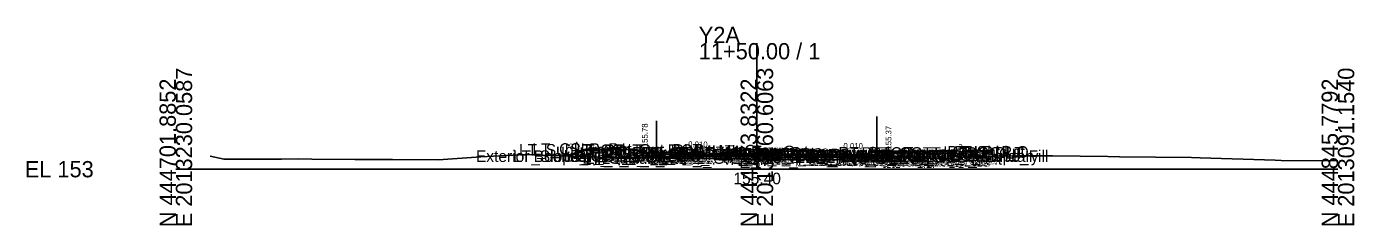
# Model space of a CAD drawing. Extents: x -26 to 203, y -10 to 5517.
# Drawn here: x -25.7 to 202.8, y 2990.3 to 3024.6 of the extents above; entities that cross this region are included whole.
import ezdxf

# ---------------------------------------------------------------- set-up
doc = ezdxf.new("R2010")
doc.units = 0
for name, color, linetype in [('Default', 7, 'Continuous'), ('Exist Cross Section Cell', 7, 'Continuous'), ('Exist XS Center Line Elevation Label', 7, 'Continuous'), ('Exist XS Ground Line', 7, 'Continuous'), ('Prop CMT Conc Surface', 7, 'Continuous'), ('Prop CMT Concrete Structures', 7, 'Continuous'), ('Prop CMT Pvmt Course 1', 7, 'Continuous'), ('Prop CMT Pvmt Course 1 CG', 7, 'Continuous'), ('Prop CMT Pvmt Course 2', 7, 'Continuous'), ('Prop CMT Pvmt Course 2 Wedge', 7, 'Continuous'), ('Prop CMT Pvmt Course 3', 7, 'Continuous'), ('Prop CMT Pvmt Surface', 7, 'Continuous'), ('Prop CMT Pvmt Wedge Surface 1', 7, 'Continuous'), ('Prop CMT Pvmt Wedge Surface 2', 7, 'Continuous'), ('Prop CMT Pvmt Wedge Surface 3', 7, 'Continuous'), ('Prop CMT Slope Grass', 7, 'Continuous'), ('Prop CMT Subgrade Earthwork', 7, 'Continuous'), ('Prop XS Earthwork Shape', 7, 'Continuous'), ('Prop XS Hydro Elevations', 7, 'Continuous'), ('Prop XS SE Text', 7, 'Continuous'), ('Prop XS Side Slope Text', 7, 'Continuous'), ('Prop XS Wedging', 7, 'Continuous'), ('Scratch_Level_0', 7, 'Continuous'), ('Scratch_Level_3', 7, 'Continuous')]:
    doc.layers.add(name, color=color, linetype=linetype)

msp = doc.modelspace()

# ---------------------------------------------------------------- linework, layer by layer
at = {"layer": 'Exist Cross Section Cell'}
for p, q in [((100, 3000), (100, 3021.72)), ((0, 3000), (100, 3000)), ((100, 3000), (200, 3000))]:
    msp.add_line(p, q, dxfattribs=at)
at = {"layer": 'Exist XS Ground Line'}
msp.add_lwpolyline([(5.88, 3002.27), (8.3, 3001.72), (18.19, 3001.71), (21.12, 3001.81), (23.4, 3001.71), (30.82, 3001.65), (37.3, 3001.65), (45.22, 3001.61), (52.5, 3002.13), (60.19, 3002.53), (62.95, 3002.4), (73.11, 3002.05), (79, 3001.94), (88.42, 3002.24), (90.7, 3002.26), (94.3, 3002.27), (100, 3002.4), (102.78, 3002.47), (109.36, 3002.44), (109.79, 3001.94), (110.4, 3001.97), (111.44, 3002.03), (115.23, 3002.09), (122.24, 3002.25), (131.43, 3001.8), (133.48, 3001.76), (134.2, 3001.73), (135.17, 3001.68), (135.61, 3002.18), (139.05, 3002.2), (140.92, 3002.22), (144.66, 3002.29), (150.86, 3002.31), (160.42, 3002.18), (162.4, 3002.14), (174.82, 3001.99), (176.3, 3001.96), (189.22, 3001.54), (190.21, 3001.52), (200, 3001.45)], dxfattribs=at)
at = {"layer": 'Prop CMT Conc Surface'}
for points in [[(80.71, 3002.79), (80.71, 3003.29), (80.21, 3003.29)], [(82.71, 3002.85), (80.71, 3002.79)], [(120.65, 3002.47), (122.65, 3002.37)], [(122.65, 3002.37), (122.65, 3002.87), (123.15, 3002.87)]]:
    msp.add_lwpolyline(points, dxfattribs=at)
at = {"layer": 'Prop CMT Concrete Structures'}
for points in [[(82.71, 3002.85), (80.71, 3002.79), (80.71, 3003.29), (80.21, 3003.29)], [(80.21, 3003.29), (80.21, 3002.29), (82.71, 3002.26)], [(132.89, 3003.07), (127.53, 3002.96)], [(127.53, 3002.96), (127.53, 3002.63)], [(132.89, 3002.74), (132.89, 3003.07)], [(82.71, 3002.26), (82.71, 3002.85)], [(96.38, 3002.71), (104.26, 3002.63)], [(120.65, 3002.47), (122.65, 3002.37), (122.65, 3002.87), (123.15, 3002.87)], [(123.15, 3002.87), (123.15, 3001.86), (120.65, 3001.88)], [(120.65, 3001.88), (120.65, 3002.47)], [(127.53, 3002.63), (132.89, 3002.74)]]:
    msp.add_lwpolyline(points, dxfattribs=at)
at = {"layer": 'Prop CMT Pvmt Course 1'}
for points in [[(96.38, 3002.71), (82.71, 3002.85)], [(82.71, 3002.85), (82.71, 3002.6)], [(82.71, 3002.6), (119.61, 3002.23)], [(96.38, 3002.46), (96.38, 3002.71)], [(96.38, 3002.71), (104.26, 3002.63)], [(96.38, 3002.46), (96.38, 3002.71)], [(96.38, 3002.58), (96.38, 3002.46), (96.38, 3002.46)], [(104.26, 3002.38), (96.38, 3002.46)], [(104.26, 3002.63), (120.65, 3002.47)], [(104.26, 3002.38), (104.26, 3002.63)], [(104.26, 3002.63), (104.26, 3002.38)], [(104.26, 3002.51), (104.26, 3002.38), (104.26, 3002.38)], [(120.65, 3002.22), (119.65, 3002.23)], [(120.65, 3002.47), (120.65, 3002.22)]]:
    msp.add_lwpolyline(points, dxfattribs=at)
at = {"layer": 'Prop CMT Pvmt Course 1 CG'}
for points in [[(82.71, 3002.26), (79.71, 3002.29), (79.38, 3001.96)], [(79.38, 3001.96), (82.71, 3001.93)], [(82.71, 3001.93), (82.71, 3002.26)], [(120.65, 3001.88), (123.65, 3001.85), (123.98, 3001.52)], [(120.65, 3001.55), (120.65, 3001.88)], [(123.98, 3001.52), (120.65, 3001.55)]]:
    msp.add_lwpolyline(points, dxfattribs=at)
at = {"layer": 'Prop CMT Pvmt Course 2'}
for points in [[(119.61, 3002.23), (82.71, 3002.6)], [(82.71, 3002.6), (82.71, 3002.26)], [(96.38, 3002.46), (104.26, 3002.38)], [(96.38, 3002.13), (96.38, 3002.46)], [(104.26, 3002.05), (96.38, 3002.13)], [(104.26, 3002.38), (104.26, 3002.05)], [(119.65, 3002.23), (120.65, 3002.22)], [(120.65, 3001.88), (119.65, 3001.89)], [(120.65, 3002.22), (120.65, 3001.88)]]:
    msp.add_lwpolyline(points, dxfattribs=at)
at = {"layer": 'Prop CMT Pvmt Course 2 Wedge'}
msp.add_lwpolyline([(104.26, 3002.38), (119.61, 3002.23)], dxfattribs=at)
at = {"layer": 'Prop CMT Pvmt Course 3'}
for points in [[(82.71, 3002.26), (82.71, 3001.93)], [(82.71, 3002.26), (96.38, 3002.13)], [(82.71, 3001.93), (120.65, 3001.55)], [(96.38, 3002.13), (104.26, 3002.05)], [(96.38, 3001.79), (96.38, 3002.13)], [(104.26, 3001.71), (96.38, 3001.79)], [(104.26, 3002.05), (120.61, 3001.88)], [(104.26, 3002.05), (104.26, 3001.71)], [(120.65, 3001.88), (120.65, 3001.55)]]:
    msp.add_lwpolyline(points, dxfattribs=at)
at = {"layer": 'Prop CMT Pvmt Surface'}
for points in [[(96.38, 3002.71), (82.71, 3002.85)], [(96.38, 3002.71), (104.26, 3002.63)], [(104.26, 3002.63), (120.65, 3002.47)]]:
    msp.add_lwpolyline(points, dxfattribs=at)
at = {"layer": 'Prop CMT Pvmt Wedge Surface 1'}
for points in [[(104.26, 3002.63), (104.26, 3002.38), (104.26, 3002.38), (104.26, 3002.51)], [(119.65, 3002.23), (120.65, 3002.22)], [(120.65, 3002.22), (120.65, 3002.47)]]:
    msp.add_lwpolyline(points, dxfattribs=at)
at = {"layer": 'Prop CMT Pvmt Wedge Surface 2'}
for points in [[(104.26, 3002.63), (104.26, 3002.38)], [(104.26, 3002.38), (120.61, 3002.22)], [(120.65, 3002.22), (120.65, 3002.47)]]:
    msp.add_lwpolyline(points, dxfattribs=at)
at = {"layer": 'Prop CMT Pvmt Wedge Surface 3'}
for points in [[(104.26, 3002.63), (104.26, 3002.05)], [(120.65, 3001.88), (120.65, 3002.47)]]:
    msp.add_lwpolyline(points, dxfattribs=at)
at = {"layer": 'Prop CMT Slope Grass'}
for points in [[(80.21, 3003.29), (70.71, 3003.48), (67.06, 3002.26)], [(123.15, 3002.87), (132.89, 3003.06)], [(132.89, 3003.06), (133.39, 3003.07), (136.06, 3002.18)]]:
    msp.add_lwpolyline(points, dxfattribs=at)
at = {"layer": 'Prop CMT Subgrade Earthwork'}
for points in [[(82.71, 3001.93), (79.38, 3001.96), (78.02, 3003.33)], [(120.65, 3001.55), (82.71, 3001.93)], [(96.38, 3001.79), (104.26, 3001.71)], [(120.65, 3001.55), (123.98, 3001.52), (125.38, 3002.91)]]:
    msp.add_lwpolyline(points, dxfattribs=at)
at = {"layer": 'Prop XS Earthwork Shape'}
for points in [[(79.85, 3001.97), (78.49, 3003.32), (71.19, 3003.47), (67.5, 3002.24), (73.11, 3002.05), (79, 3001.94)], [(125.34, 3002.91), (127.48, 3002.96), (127.48, 3002.63), (132.85, 3002.74), (132.85, 3003.06), (133.35, 3003.07), (136.02, 3002.18), (135.61, 3002.18), (135.17, 3001.68), (134.2, 3001.73), (133.48, 3001.76), (131.43, 3001.8), (124.56, 3002.14)], [(109.79, 3001.94), (110.4, 3001.97), (111.44, 3002.03), (115.23, 3002.09), (120.61, 3002.21), (120.61, 3001.88), (123.11, 3001.86), (123.11, 3002.21), (124.56, 3002.14), (123.94, 3001.52), (120.61, 3001.55), (119.61, 3001.56), (104.26, 3001.71), (96.38, 3001.79), (83.19, 3001.92), (79.86, 3001.96), (79.85, 3001.97), (88.42, 3002.24), (90.7, 3002.26), (94.3, 3002.27), (100, 3002.4), (102.78, 3002.47), (109.36, 3002.44)], [(123.11, 3002.21), (123.11, 3001.86), (120.61, 3001.88), (120.61, 3002.21), (122.24, 3002.25)]]:
    msp.add_lwpolyline(points, close=True, dxfattribs=at)
at = {"layer": 'Prop XS Wedging'}
for p, q in [((94.11, 3002.48), (83.19, 3002.59)), ((83.19, 3002.59), (83.19, 3002.26)), ((83.19, 3002.26), (83.19, 3002.07)), ((83.19, 3002.07), (88.42, 3002.24)), ((94.32, 3002.27), (94.11, 3002.48)), ((96.38, 3002.46), (94.11, 3002.48)), ((94.11, 3002.48), (94.32, 3002.27)), ((94.32, 3002.27), (94.11, 3002.48)), ((94.32, 3002.27), (96.38, 3002.32)), ((96.38, 3002.32), (96.38, 3002.46))]:
    msp.add_line(p, q, dxfattribs=at)
msp.add_lwpolyline([(88.42, 3002.24), (90.7, 3002.26), (94.3, 3002.27), (94.32, 3002.27)], dxfattribs=at)
at = {"layer": 'Scratch_Level_3'}
for p, q in [((82.71, 3002.85), (82.71, 3008.3)), ((120.65, 3002.47), (120.65, 3009.1))]:
    msp.add_line(p, q, dxfattribs=at)

# ---------------------------------------------------------------- texts
at = {"layer": 'Default'}
msp.add_text('-', height=0.0001, dxfattribs=at).set_placement((0, 3000))
at = {"layer": 'Exist Cross Section Cell'}
for s, p in [('Y2A', (90, 3021.72)), ('11+50.00 / 1', (90, 3018.92)), ('EL 153', (-26, 2998.6))]:
    msp.add_text(s, height=2.8, dxfattribs=at).set_placement(p)
for s, p in [('E 2013230.0587', (2.8, 2990)), ('E 2013160.6063', (102.8, 2990)), ('E 2013091.1540', (202.8, 2990)), ('N 444701.8852', (0, 2990)), ('N 444773.8322', (100, 2990)), ('N 444845.7792', (200, 2990))]:
    msp.add_text(s, height=2.8, rotation=90, dxfattribs=at).set_placement(p)
at = {"layer": 'Exist XS Center Line Elevation Label'}
msp.add_text('155.40', height=2, dxfattribs=at).set_placement((95.95, 2997.4))
at = {"layer": 'Prop XS Hydro Elevations'}
for s, p in [('155.78', (81.21, 3003.79)), ('155.37', (123.15, 3003.37))]:
    msp.add_text(s, height=1, rotation=90, dxfattribs=at).set_placement(p)
at = {"layer": 'Prop XS SE Text'}
for p in [(88.17, 3003.79), (114.89, 3003.52)]:
    msp.add_text('0.010', height=1, rotation=359.4271, dxfattribs=at).set_placement(p)
at = {"layer": 'Prop XS Side Slope Text'}
for rotation, p in [(18.4349, (67.88, 3003.32)), (341.5668, (134.46, 3003.47))]:
    msp.add_text('3:1', height=1, rotation=rotation, dxfattribs=at).set_placement(p)
at = {"layer": 'Scratch_Level_0'}
for s, p in [('Exterior Boundary', (51.64, 3001.24)), ('LT_Slope_Fill', (58.02, 3001.24)), ('LT_Sub_Trench_Out_DLT', (59.06, 3002.32)), ('LT_CSLP_Pnt', (61.36, 3002.47)), ('LT_CG1_Shelf_Out', (66.74, 3001.29)), ('LT_CG_Top_Face', (68.45, 3002.28)), ('LT_CG_Top_BOC', (68.97, 3002.28)), ('LT_CG_Bot_BOC', (69, 3001.28)), ('LT_CG_Top_Gut', (69.43, 3001.78)), ('LT_Sub_OEOP', (69.97, 3000.96)), ('LT_Sub_OEOT_CG', (70.56, 3000.92)), ('LT_CG_Bot_IE', (73.1, 3001.26)), ('LT_Sub_OEOT', (73.27, 3000.92)), ('LT_PV2_OEOT', (73.36, 3001.59)), ('LT_PV3_OEOT', (73.36, 3001.26)), ('LT_PV1_OEOT', (73.93, 3001.84)), ('LT_PV2_IEEOP', (86.34, 3001.46)), ('LT_PV1_IEEOP', (86.9, 3001.58)), ('LT_PV2_PGL1', (87.26, 3001.46)), ('LT_PV3_PGL1', (87.26, 3001.13)), ('LT_PV2_PGL', (87.6, 3001.46)), ('LT_PV1_PGL', (88.16, 3001.71)), ('MI_Face In', (88.28, 3001.88)), ('MI_Top In', (89.99, 3002.13)), ('RT_PV_IEEOP_EG', (92.4, 3001.46)), ('MI_Crown', (93.39, 3002.19)), ('RT_PV2_IEEOP', (94.17, 3001.38)), ('RT_PV3_IEEOP', (94.17, 3001.05)), ('MI_Face Out', (94.52, 3001.8)), ('MI_Top Out', (94.73, 3002.05)), ('RT_PV1_IEEOP', (94.74, 3001.51)), ('RT_PV2_PGL1', (95.1, 3001.38)), ('RT_PV3_PGL1', (95.1, 3001.05)), ('RT_PV2_PGL', (95.43, 3001.38)), ('RT_PV3_PGL', (95.43, 3001.05)), ('MI_Bot Out', (95.52, 3001.63)), ('RT_PV1_PGL', (96, 3001.63)), ('RT_PV_EG_TestPt', (98.3, 3001.04)), ('RT_PV_Sub_Tie_Out', (104.49, 3001.19)), ('RT_PV_OEEOP_EG', (107.1, 3001.19)), ('RT_PV2_OEEOP', (108.87, 3001.23)), ('RT_PV3_OEEOP', (108.87, 3000.89)), ('LT_PV2_OEEOP', (108.91, 3001.23)), ('LT_PV3_OEEOP', (108.91, 3000.89)), ('RT_PV1_OEEOP', (109.43, 3001.35)), ('LT_PV1_OEEOP', (109.48, 3001.35)), ('RT_Sub_Trench_Out_DLT', (114, 3001.83)), ('RT_CG_Top_Face', (117.96, 3001.79)), ('RT_PV2_OEOT', (118.88, 3001.14)), ('RT_CG_Top_Gut', (118.94, 3001.29)), ('RT_PV1_OEOT', (119.44, 3001.39)), ('RT_CG_Top_BOC', (119.49, 3001.79)), ('Exterior Boundary', (127.05, 3001.26)), ('RT_Shld_O', (132.79, 3001.97)), ('RT_Slope_Fill', (133.38, 3001.26)), ('CSLP_Pnt', (133.62, 3001.98)), ('LT_PV4_PGL', (87.6, 3000.79)), ('RT_PV4_PGL', (95.43, 3000.71)), ('RT_Sub_OEEOP', (108.77, 3000.56)), ('LT_Sub_OEEOP', (108.82, 3000.56)), ('RT_Sub_OEOT_CG', (116.07, 3000.47)), ('RT_CG1_Shelf_Out', (118.25, 3000.77)), ('RT_CG_Bot_IE', (118.62, 3000.8)), ('RT_Sub_OEOT', (118.78, 3000.47)), ('RT_PV3_OEOT', (118.88, 3000.8)), ('RT_CG_Bot_BOC', (119.52, 3000.78)), ('RT_Sub_OEOP', (122.15, 3000.44))]:
    msp.add_text(s, height=2, dxfattribs=at).set_placement(p)

doc.saveas('drawing.dxf')
